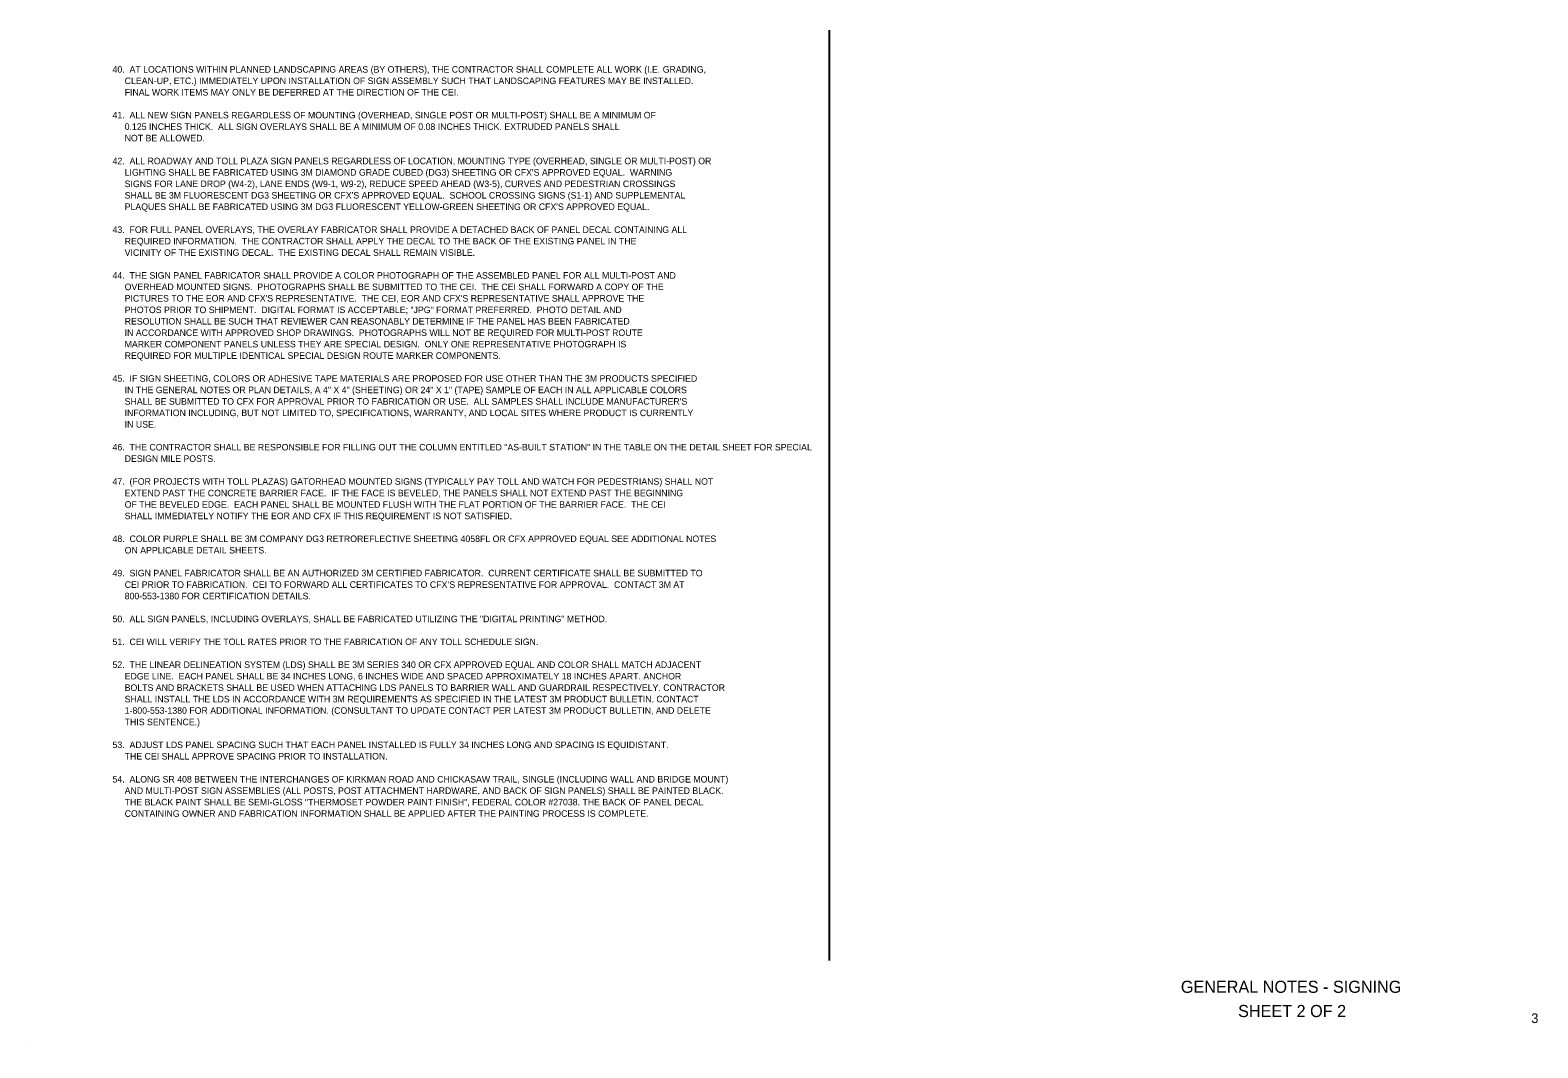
# Model space of a CAD drawing. Extents: x 2479953 to 2481508, y 3678869 to 3679919.
import ezdxf

# ---------------------------------------------------------------- set-up
doc = ezdxf.new("R2010")
doc.units = 0
for name, color, linetype in [('AdhocPoint_dp', 7, 'Continuous'), ('NonPlottingEle_dp', 7, 'Continuous'), ('TextLabel', 7, 'Continuous'), ('TextMisc', 7, 'Continuous'), ('TextShtNo', 7, 'Continuous')]:
    doc.layers.add(name, color=color, linetype=linetype)

msp = doc.modelspace()

# ---------------------------------------------------------------- linework, layer by layer
at = {"layer": 'AdhocPoint_dp'}
msp.add_line((2479952.6, 3678869), (2479952.6, 3678869), dxfattribs=at)
at = {"layer": 'NonPlottingEle_dp'}
msp.add_line((2480777.6, 3678959), (2480777.6, 3679919), dxfattribs=at)

# ---------------------------------------------------------------- texts
at = {"layer": 'TextLabel'}
for s, p in [('40.  AT LOCATIONS WITHIN PLANNED LANDSCAPING AREAS (BY OTHERS), THE CONTRACTOR SHALL COMPLETE ALL WORK (I.E. GRADING,', (2480037.6, 3679875.2)), ('     CLEAN-UP, ETC.) IMMEDIATELY UPON INSTALLATION OF SIGN ASSEMBLY SUCH THAT LANDSCAPING FEATURES MAY BE INSTALLED.', (2480037.6, 3679863.4)), ('     FINAL WORK ITEMS MAY ONLY BE DEFERRED AT THE DIRECTION OF THE CEI.', (2480037.6, 3679851.6)), ('41.  ALL NEW SIGN PANELS REGARDLESS OF MOUNTING (OVERHEAD, SINGLE POST OR MULTI-POST) SHALL BE A MINIMUM OF', (2480037.6, 3679828)), ('     0.125 INCHES THICK.  ALL SIGN OVERLAYS SHALL BE A MINIMUM OF 0.08 INCHES THICK. EXTRUDED PANELS SHALL', (2480037.6, 3679816.1)), ('     NOT BE ALLOWED.', (2480037.6, 3679804.3)), ('42.  ALL ROADWAY AND TOLL PLAZA SIGN PANELS REGARDLESS OF LOCATION, MOUNTING TYPE (OVERHEAD, SINGLE OR MULTI-POST) OR', (2480037.6, 3679780.7)), ("     LIGHTING SHALL BE FABRICATED USING 3M DIAMOND GRADE CUBED (DG3) SHEETING OR CFX'S APPROVED EQUAL.  WARNING", (2480037.6, 3679768.9)), ('     SIGNS FOR LANE DROP (W4-2), LANE ENDS (W9-1, W9-2), REDUCE SPEED AHEAD (W3-5), CURVES AND PEDESTRIAN CROSSINGS', (2480037.6, 3679757.1)), ("     SHALL BE 3M FLUORESCENT DG3 SHEETING OR CFX'S APPROVED EQUAL.  SCHOOL CROSSING SIGNS (S1-1) AND SUPPLEMENTAL", (2480037.6, 3679745.3)), ("     PLAQUES SHALL BE FABRICATED USING 3M DG3 FLUORESCENT YELLOW-GREEN SHEETING OR CFX'S APPROVED EQUAL.", (2480037.6, 3679733.5)), ('43.  FOR FULL PANEL OVERLAYS, THE OVERLAY FABRICATOR SHALL PROVIDE A DETACHED BACK OF PANEL DECAL CONTAINING ALL', (2480037.6, 3679709.8)), ('     REQUIRED INFORMATION.  THE CONTRACTOR SHALL APPLY THE DECAL TO THE BACK OF THE EXISTING PANEL IN THE', (2480037.6, 3679698)), ('     VICINITY OF THE EXISTING DECAL.  THE EXISTING DECAL SHALL REMAIN VISIBLE.', (2480037.6, 3679686.2)), ('44.  THE SIGN PANEL FABRICATOR SHALL PROVIDE A COLOR PHOTOGRAPH OF THE ASSEMBLED PANEL FOR ALL MULTI-POST AND', (2480037.6, 3679662.6)), ('     OVERHEAD MOUNTED SIGNS.  PHOTOGRAPHS SHALL BE SUBMITTED TO THE CEI.  THE CEI SHALL FORWARD A COPY OF THE', (2480037.6, 3679650.8)), ("     PICTURES TO THE EOR AND CFX'S REPRESENTATIVE.  THE CEI, EOR AND CFX'S REPRESENTATIVE SHALL APPROVE THE", (2480037.6, 3679639)), ('     PHOTOS PRIOR TO SHIPMENT.  DIGITAL FORMAT IS ACCEPTABLE; "JPG" FORMAT PREFERRED.  PHOTO DETAIL AND', (2480037.6, 3679627.1)), ('     RESOLUTION SHALL BE SUCH THAT REVIEWER CAN REASONABLY DETERMINE IF THE PANEL HAS BEEN FABRICATED', (2480037.6, 3679615.3)), ('     IN ACCORDANCE WITH APPROVED SHOP DRAWINGS.  PHOTOGRAPHS WILL NOT BE REQUIRED FOR MULTI-POST ROUTE', (2480037.6, 3679603.5)), ('     MARKER COMPONENT PANELS UNLESS THEY ARE SPECIAL DESIGN.  ONLY ONE REPRESENTATIVE PHOTOGRAPH IS', (2480037.6, 3679591.7)), ('     REQUIRED FOR MULTIPLE IDENTICAL SPECIAL DESIGN ROUTE MARKER COMPONENTS.', (2480037.6, 3679579.9)), ('45.  IF SIGN SHEETING, COLORS OR ADHESIVE TAPE MATERIALS ARE PROPOSED FOR USE OTHER THAN THE 3M PRODUCTS SPECIFIED', (2480037.6, 3679556.3)), ("     SHALL BE SUBMITTED TO CFX FOR APPROVAL PRIOR TO FABRICATION OR USE.  ALL SAMPLES SHALL INCLUDE MANUFACTURER'S", (2480037.6, 3679532.6)), ('     IN THE GENERAL NOTES OR PLAN DETAILS, A 4" X 4" (SHEETING) OR 24" X 1" (TAPE) SAMPLE OF EACH IN ALL APPLICABLE COLORS', (2480037.6, 3679544.5)), ('     INFORMATION INCLUDING, BUT NOT LIMITED TO, SPECIFICATIONS, WARRANTY, AND LOCAL SITES WHERE PRODUCT IS CURRENTLY', (2480037.6, 3679520.8)), ('     IN USE.', (2480037.6, 3679509)), ('46.  THE CONTRACTOR SHALL BE RESPONSIBLE FOR FILLING OUT THE COLUMN ENTITLED "AS-BUILT STATION" IN THE TABLE ON THE DETAIL SHEET FOR SPECIAL', (2480037.6, 3679485.4)), ('     DESIGN MILE POSTS.', (2480037.6, 3679473.6)), ('47.  (FOR PROJECTS WITH TOLL PLAZAS) GATORHEAD MOUNTED SIGNS (TYPICALLY PAY TOLL AND WATCH FOR PEDESTRIANS) SHALL NOT', (2480037.6, 3679450)), ('     OF THE BEVELED EDGE.  EACH PANEL SHALL BE MOUNTED FLUSH WITH THE FLAT PORTION OF THE BARRIER FACE.  THE CEI', (2480037.6, 3679426.3)), ('     EXTEND PAST THE CONCRETE BARRIER FACE.  IF THE FACE IS BEVELED, THE PANELS SHALL NOT EXTEND PAST THE BEGINNING', (2480037.6, 3679438.1)), ('     SHALL IMMEDIATELY NOTIFY THE EOR AND CFX IF THIS REQUIREMENT IS NOT SATISFIED.', (2480037.6, 3679414.5)), ('48.  COLOR PURPLE SHALL BE 3M COMPANY DG3 RETROREFLECTIVE SHEETING 4058FL OR CFX APPROVED EQUAL SEE ADDITIONAL NOTES', (2480037.6, 3679390.9)), ('     ON APPLICABLE DETAIL SHEETS.', (2480037.6, 3679379.1)), ('49.  SIGN PANEL FABRICATOR SHALL BE AN AUTHORIZED 3M CERTIFIED FABRICATOR.  CURRENT CERTIFICATE SHALL BE SUBMITTED TO', (2480037.6, 3679355.5)), ('     800-553-1380 FOR CERTIFICATION DETAILS.', (2480037.6, 3679331.8)), ('     CEI PRIOR TO FABRICATION.  CEI TO FORWARD ALL CERTIFICATES TO CFX’S REPRESENTATIVE FOR APPROVAL.  CONTACT 3M AT', (2480037.6, 3679343.6)), ('50.  ALL SIGN PANELS, INCLUDING OVERLAYS, SHALL BE FABRICATED UTILIZING THE "DIGITAL PRINTING" METHOD.', (2480037.6, 3679308.2)), ('51.  CEI WILL VERIFY THE TOLL RATES PRIOR TO THE FABRICATION OF ANY TOLL SCHEDULE SIGN.', (2480037.6, 3679284.6)), ('52.  THE LINEAR DELINEATION SYSTEM (LDS) SHALL BE 3M SERIES 340 OR CFX APPROVED EQUAL AND COLOR SHALL MATCH ADJACENT ', (2480037.6, 3679261)), ('     EDGE LINE.  EACH PANEL SHALL BE 34 INCHES LONG, 6 INCHES WIDE AND SPACED APPROXIMATELY 18 INCHES APART. ANCHOR ', (2480037.6, 3679249.1)), ('     BOLTS AND BRACKETS SHALL BE USED WHEN ATTACHING LDS PANELS TO BARRIER WALL AND GUARDRAIL RESPECTIVELY. CONTRACTOR ', (2480037.6, 3679237.3)), ('     SHALL INSTALL THE LDS IN ACCORDANCE WITH 3M REQUIREMENTS AS SPECIFIED IN THE LATEST 3M PRODUCT BULLETIN. CONTACT ', (2480037.6, 3679225.5)), ('     1-800-553-1380 FOR ADDITIONAL INFORMATION. (CONSULTANT TO UPDATE CONTACT PER LATEST 3M PRODUCT BULLETIN, AND DELETE ', (2480037.6, 3679213.7)), ('     THIS SENTENCE.)', (2480037.6, 3679201.9)), ('53.  ADJUST LDS PANEL SPACING SUCH THAT EACH PANEL INSTALLED IS FULLY 34 INCHES LONG AND SPACING IS EQUIDISTANT.', (2480037.6, 3679178.3)), ('     THE CEI SHALL APPROVE SPACING PRIOR TO INSTALLATION.', (2480037.6, 3679166.5)), ('54.  ALONG SR 408 BETWEEN THE INTERCHANGES OF KIRKMAN ROAD AND CHICKASAW TRAIL, SINGLE (INCLUDING WALL AND BRIDGE MOUNT) ', (2480037.6, 3679142.8)), ('     AND MULTI-POST SIGN ASSEMBLIES (ALL POSTS, POST ATTACHMENT HARDWARE, AND BACK OF SIGN PANELS) SHALL BE PAINTED BLACK.', (2480037.6, 3679131)), ('     THE BLACK PAINT SHALL BE SEMI-GLOSS "THERMOSET POWDER PAINT FINISH", FEDERAL COLOR #27038. THE BACK OF PANEL DECAL', (2480037.6, 3679119.2)), ('     CONTAINING OWNER AND FABRICATION INFORMATION SHALL BE APPLIED AFTER THE PAINTING PROCESS IS COMPLETE.', (2480037.6, 3679107.4))]:
    msp.add_text(s, height=6.75, dxfattribs=at).set_placement(p)
at = {"layer": 'TextMisc'}
for s, p in [('GENERAL NOTES - SIGNING ', (2481140, 3678925.8)), ('      SHEET 2 OF 2      ', (2481171.2, 3678900.8))]:
    msp.add_text(s, height=12.5, rotation=360, dxfattribs=at).set_placement(p)
at = {"layer": 'TextShtNo'}
msp.add_text('  3  ', height=10, rotation=360, dxfattribs=at).set_placement((2481494.1, 3678894.6))

doc.saveas('drawing.dxf')
